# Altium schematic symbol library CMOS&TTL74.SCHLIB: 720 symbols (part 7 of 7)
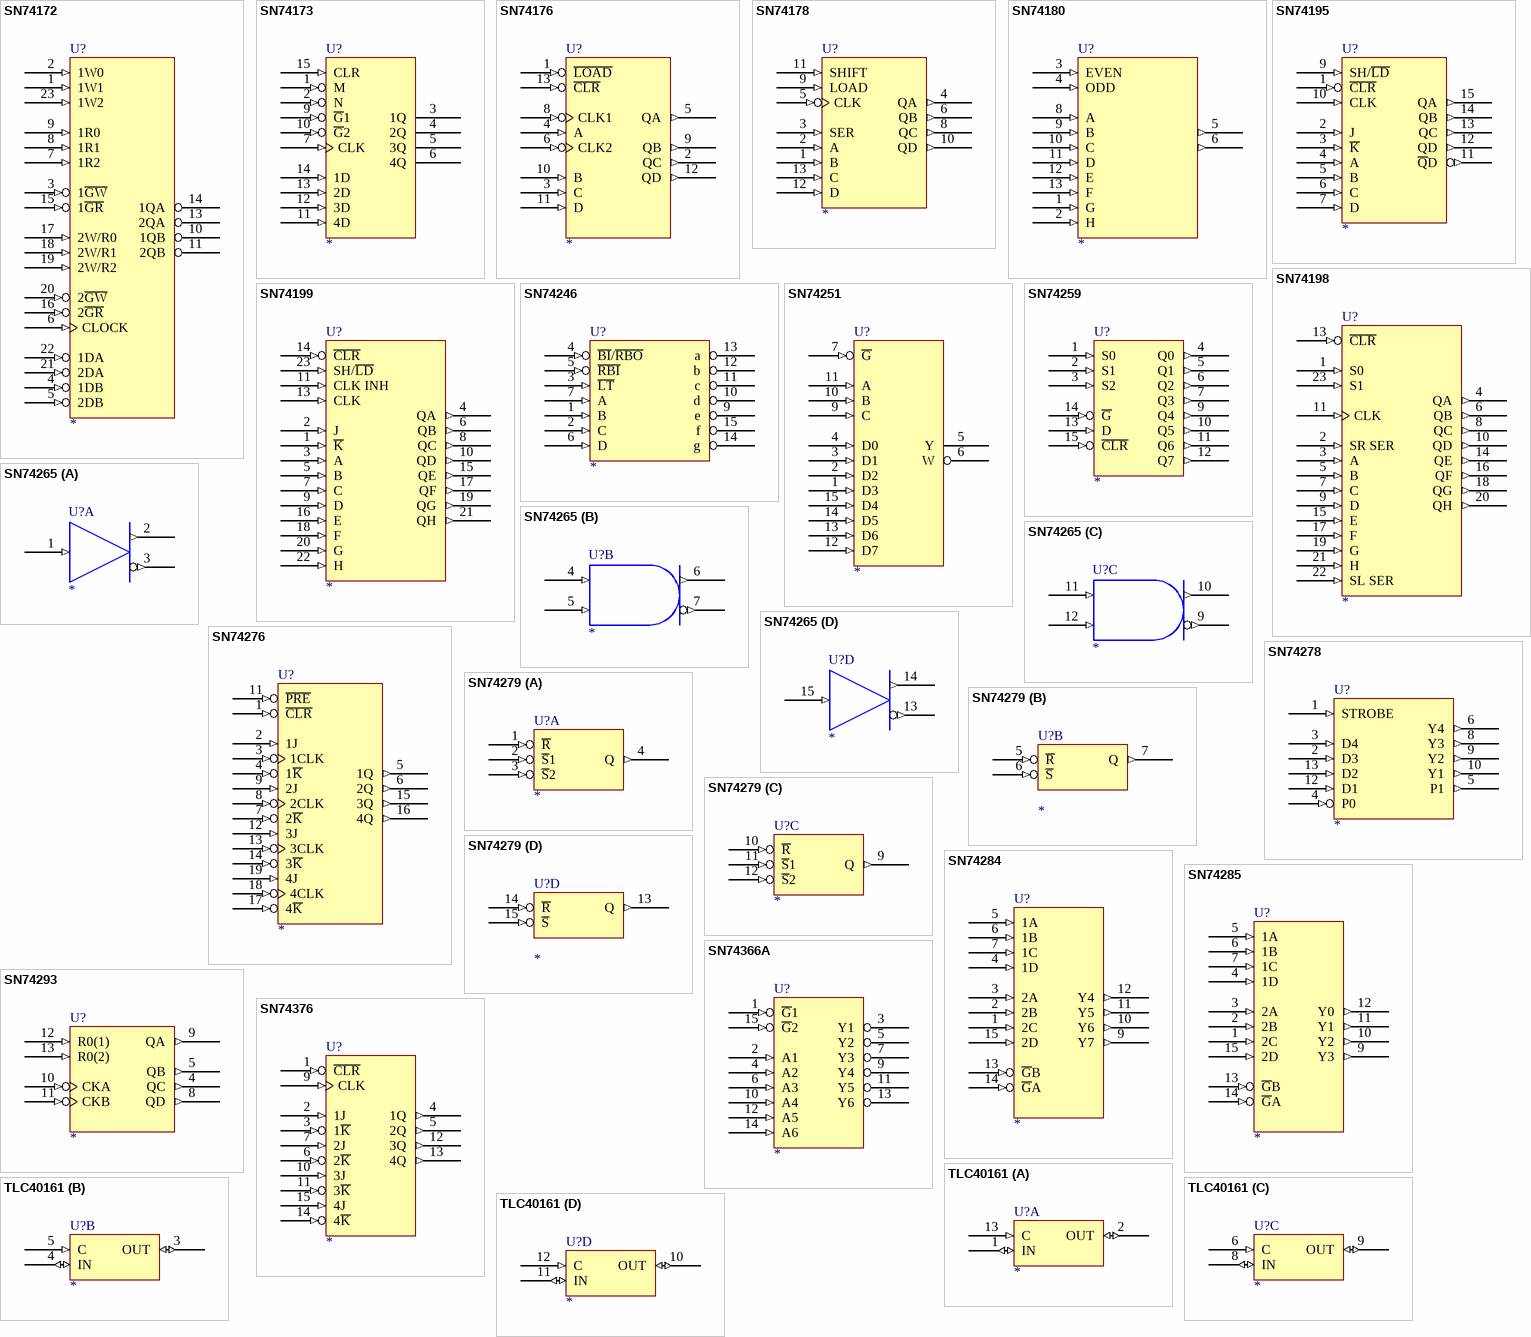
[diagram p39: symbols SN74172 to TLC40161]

## SN74276
designator U?
QUAD JK FF
footprint DIP-20
pins: 1 ~{CLR} (in), 2 1J (in), 3 1CLK (in), 4 1~{K} (in), 5 1Q (out), 6 2Q (out), 7 2~{K} (in), 8 2CLK (in), 9 2J (in), 10 GND (power) hidden to GND, 11 ~{PRE} (in), 12 3J (in), 13 3CLK (in), 14 3~{K} (in), 15 3Q (out), 16 4Q (out), 17 4~{K} (in), 18 4CLK (in), 19 4J (in), 20 VCC (power) hidden to VCC
1 alternate drawing of the same symbol

## SN74278
designator U?
f4-BIT CASCADED PRIORITY REG
footprint DIP-14
pins: 1 STROBE (in), 2 D3 (in), 3 D4 (in), 4 P0 (in), 5 P1 (out), 6 Y4 (out), 7 GND (power) hidden to GND, 8 Y3 (out), 9 Y2 (out), 10 Y1 (out), 12 D1 (in), 13 D2 (in), 14 VCC (power) hidden to VCC
1 alternate drawing of the same symbol

## SN74279
designator U?
QUAD S\-R\ LCH
footprint DIP-16
footprint SO16
part A pins: 1 ~{R} (in), 2 ~{S}1 (in), 3 ~{S}2 (in), 4 Q (out), 8 GND (power) hidden to GND, 16 VCC (power) hidden to VCC
part B pins: 5 ~{R} (in), 6 ~{S} (in), 7 Q (out), 8 GND (power) hidden to GND, 16 VCC (power) hidden to VCC
part C pins: 8 GND (power) hidden to GND, 9 Q (out), 10 ~{R} (in), 11 ~{S}1 (in), 12 ~{S}2 (in), 16 VCC (power) hidden to VCC
part D pins: 8 GND (power) hidden to GND, 13 Q (out), 14 ~{R} (in), 15 ~{S} (in), 16 VCC (power) hidden to VCC
1 alternate drawing of the same symbol

## SN74284
designator U?
4-BIT BY 4-BIT PARALLEL BIN MULT
footprint DIP-16
pins: 1 2C (in), 2 2B (in), 3 2A (in), 4 1D (in), 5 1A (in), 6 1B (in), 7 1C (in), 8 GND (power) hidden to GND, 9 Y7 (out), 10 Y6 (out), 11 Y5 (out), 12 Y4 (out), 13 ~{G}B (in), 14 ~{G}A (in), 15 2D (in), 16 VCC (power) hidden to VCC
1 alternate drawing of the same symbol

## SN74285
designator U?
4-BIT BY 4-BIT PARALLEL BIN MULT
footprint DIP-16
pins: 1 2C (in), 2 2B (in), 3 2A (in), 4 1D (in), 5 1A (in), 6 1B (in), 7 1C (in), 8 GND (power) hidden to GND, 9 Y3 (out), 10 Y2 (out), 11 Y1 (out), 12 Y0 (out), 13 ~{G}B (in), 14 ~{G}A (in), 15 2D (in), 16 VCC (power) hidden to VCC
1 alternate drawing of the same symbol

## SN74293
designator U?
DECADE AND 4-BIT BIN CNT
footprint DIP-14
footprint SO14
pins: 4 QC (out), 5 QB (out), 7 GND (power) hidden to GND, 8 QD (out), 9 QA (out), 10 CKA (in), 11 CKB (in), 12 R0(1) (in), 13 R0(2) (in), 14 VCC (power) hidden to VCC
1 alternate drawing of the same symbol

## SN74366A
designator U?
HEX BUS DRV 3SO
footprint DIP-16
footprint SO16
pins: 1 ~{G}1 (in), 2 A1 (in), 3 Y1 (hiz), 4 A2 (in), 5 Y2 (hiz), 6 A3 (in), 7 Y3 (hiz), 8 GND (power) hidden to GND, 9 Y4 (hiz), 10 A4 (in), 11 Y5 (hiz), 12 A5 (in), 13 Y6 (hiz), 14 A6 (in), 15 ~{G}2 (in), 16 VCC (power) hidden to VCC
1 alternate drawing of the same symbol

## SN74376
designator U?
QUAD J-K\ FF
footprint DIP-16
pins: 1 ~{CLR} (in), 2 1J (in), 3 1~{K} (in), 4 1Q (out), 5 2Q (out), 6 2~{K} (in), 7 2J (in), 8 GND (power) hidden to GND, 9 CLK (in), 10 3J (in), 11 3~{K} (in), 12 3Q (out), 13 4Q (out), 14 4~{K} (in), 15 4J (in), 16 VCC (power) hidden to VCC
1 alternate drawing of the same symbol

## TLC40161
designator U?
QUAD ANALOG SWITCH MULTIPLEXER
footprint SO14
footprint DIP-14
part A pins: 1 IN (io), 2 OUT (io), 7 GND (power) hidden to GND, 13 C (in), 14 VCC (power) hidden to VCC
part B pins: 3 OUT (io), 4 IN (io), 5 C (in), 7 GND (power) hidden to GND, 14 VCC (power) hidden to VCC
part C pins: 6 C (in), 7 GND (power) hidden to GND, 8 IN (io), 9 OUT (io), 14 VCC (power) hidden to VCC
part D pins: 7 GND (power) hidden to GND, 10 OUT (io), 11 IN (io), 12 C (in), 14 VCC (power) hidden to VCC
1 alternate drawing of the same symbol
